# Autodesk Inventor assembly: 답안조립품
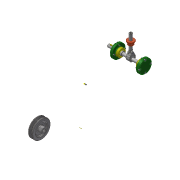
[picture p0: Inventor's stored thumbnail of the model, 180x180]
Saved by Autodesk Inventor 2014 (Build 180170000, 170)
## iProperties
Created: 2017-07
Part Number: 답안조립품
Document SubType Name: Assembly
Designer: user
Author: user
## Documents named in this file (16)
- C:\Users\user\Desktop\470708V1016\답안조립품.iam
- C:\Users\user\Desktop\470708V1016\V벨트풀리.ipt
- C:\Users\user\Desktop\470708V1016\고정핀 1.2 x  8.ipt
- C:\Users\user\Desktop\470708V1016\뒤커버.ipt
- C:\Users\user\Desktop\470708V1016\링크.ipt
- C:\Users\user\Desktop\470708V1016\멈춤나사 M3x8.ipt
- C:\Users\user\Desktop\470708V1016\베어링 12 x 32 x 10.ipt
- C:\Users\user\Desktop\470708V1016\본체.ipt
- C:\Users\user\Desktop\470708V1016\볼트 M4 x 12.ipt
- C:\Users\user\Desktop\470708V1016\부시.ipt
- C:\Users\user\Desktop\470708V1016\슬라이드.ipt
- C:\Users\user\Desktop\470708V1016\앞커버.ipt
- C:\Users\user\Desktop\470708V1016\오일실 12 25 7.ipt
- C:\Users\user\Desktop\470708V1016\키 4 x 4 x 10.ipt
- C:\Users\user\Desktop\470708V1016\편심축.ipt
- C:\Users\user\Desktop\470708V1016\핀 5 x 18.ipt
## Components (3 placed, 3 different names)
1. V벨트풀리:1
2. 고정핀 1.2 x  8:1
3. 핀 5 x 18:1
